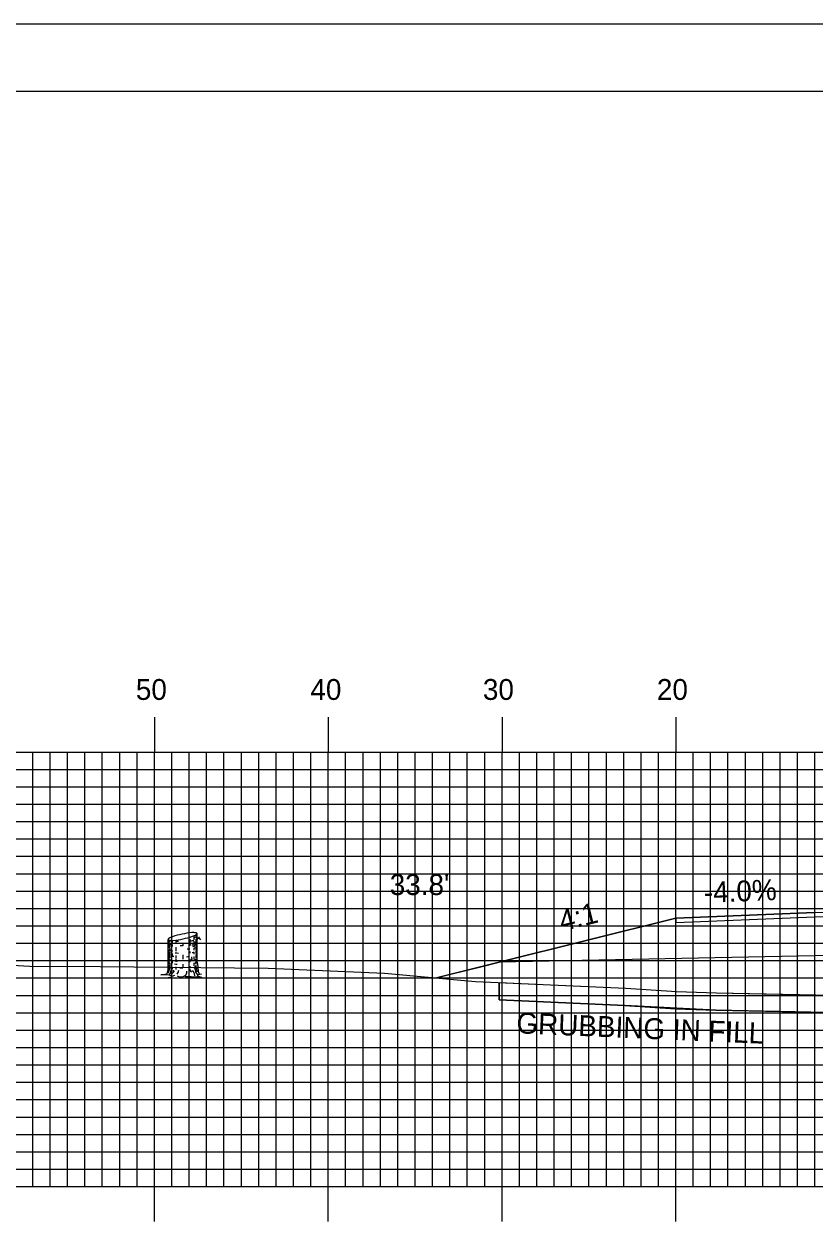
# Model space of a CAD drawing. Extents: x 1772022 to 1772366, y 442591 to 442811.
# Drawn here: x 1772130.6 to 1772176.1, y 442741.2 to 442810.5 of the extents above; entities that cross this region are included whole.
import ezdxf

# ---------------------------------------------------------------- set-up
doc = ezdxf.new("R2010")
doc.units = 0
for name, color, linetype in [('ANNOTATION', 7, 'Continuous'), ('BORDER', 7, 'Continuous'), ('D_Roadway_Centerline', 7, 'Continuous'), ('D_Roadway_Edge_Shoulder', 7, 'Continuous'), ('D_Roadway_SlopeLines', 7, 'Continuous'), ('D_Roadway_SubGrade', 7, 'Continuous'), ('D_Text_Standard', 7, 'Continuous'), ('GRUBBING IN FILL', 7, 'Continuous'), ('H_V ANNOTATION', 7, 'Continuous'), ('M_Trees_Conifer_Pay', 7, 'Continuous'), ('MAJOR', 7, 'Continuous'), ('MINOR', 7, 'Continuous'), ('PLOT BOUNDARY', 7, 'Continuous'), ('S_Roadway_Centerline', 7, 'Continuous')]:
    doc.layers.add(name, color=color, linetype=linetype)

msp = doc.modelspace()

# ---------------------------------------------------------------- linework, layer by layer
at = {"layer": 'BORDER'}
msp.add_lwpolyline([(1772038.494, 442596.665), (1772358.494, 442596.665), (1772358.494, 442806.665), (1772038.494, 442806.665)], close=True, dxfattribs=at)
at = {"layer": 'D_Roadway_Centerline'}
msp.add_lwpolyline([(1772154.321, 442755.673), (1772155.067, 442755.86), (1772156.093, 442756.116), (1772157.021, 442756.348), (1772157.919, 442756.572), (1772168.091, 442759.116), (1772168.093, 442759.116), (1772168.095, 442759.116), (1772176.094, 442759.436), (1772183.479, 442759.584), (1772188.09, 442759.676), (1772188.093, 442759.676), (1772193.883, 442759.56), (1772200.09, 442759.436), (1772200.093, 442759.436), (1772200.095, 442759.436), (1772208.094, 442759.116), (1772208.097, 442759.115), (1772218.268, 442756.572), (1772218.274, 442756.571), (1772235.086, 442752.368)], dxfattribs=at)
at = {"layer": 'D_Roadway_Edge_Shoulder'}
msp.add_lwpolyline([(1772176.094, 442759.436), (1772168.093, 442759.116), (1772168.093, 442758.866), (1772176.094, 442759.186)], close=True, dxfattribs=at)
at = {"layer": 'D_Roadway_SlopeLines'}
msp.add_lwpolyline([(1772168.093, 442759.116), (1772157.919, 442756.572), (1772156.093, 442756.116), (1772154.321, 442755.673)], dxfattribs=at)
at = {"layer": 'D_Roadway_SubGrade'}
msp.add_lwpolyline([(1772176.094, 442756.936), (1772157.919, 442756.572), (1772168.093, 442759.116), (1772168.093, 442758.866), (1772176.094, 442759.186), (1772188.093, 442759.426), (1772200.093, 442759.186), (1772208.094, 442758.866), (1772208.094, 442759.116), (1772218.268, 442756.572), (1772200.093, 442756.936), (1772188.093, 442757.176)], close=True, dxfattribs=at)
at = {"layer": 'GRUBBING IN FILL'}
msp.add_line((1772157.919, 442755.405), (1772157.919, 442754.404), dxfattribs=at)
msp.add_line((1772157.919, 442755.405), (1772157.919, 442754.404), dxfattribs=at)
msp.add_lwpolyline([(1772157.919, 442755.405), (1772160.888, 442755.272), (1772165.211, 442755.078), (1772168.132, 442754.881), (1772170.426, 442754.81), (1772180.442, 442754.609), (1772185.641, 442754.505), (1772188.094, 442754.456), (1772188.094, 442753.455), (1772180.417, 442753.609), (1772170.4, 442753.81), (1772165.155, 442754.08), (1772157.919, 442754.404)], close=True, dxfattribs=at)
msp.add_lwpolyline([(1772157.919, 442755.405), (1772160.888, 442755.272), (1772165.211, 442755.078), (1772168.132, 442754.881), (1772170.426, 442754.81), (1772180.442, 442754.609), (1772185.641, 442754.505), (1772188.094, 442754.456), (1772188.094, 442753.455), (1772180.417, 442753.609), (1772170.4, 442753.81), (1772165.155, 442754.08), (1772157.919, 442754.404)], close=True, dxfattribs=at)
msp.add_lwpolyline([(1772157.919, 442754.404), (1772165.155, 442754.08), (1772168.083, 442753.882), (1772170.4, 442753.81), (1772190.435, 442753.408), (1772192.574, 442753.345), (1772202.543, 442752.825), (1772212.888, 442752.544), (1772215.62, 442752.389), (1772218.268, 442752.3)], dxfattribs=at)
msp.add_lwpolyline([(1772157.919, 442754.404), (1772165.155, 442754.08), (1772168.083, 442753.882), (1772170.4, 442753.81), (1772190.435, 442753.408), (1772192.574, 442753.345), (1772202.543, 442752.825), (1772212.888, 442752.544), (1772215.62, 442752.389), (1772218.268, 442752.3)], dxfattribs=at)
at = {"layer": 'M_Trees_Conifer_Pay'}
for p, q in [((1772140.47, 442758.147), (1772140.47, 442757.985)), ((1772140.542, 442756.572), (1772140.542, 442758.219)), ((1772138.878, 442756.162), (1772138.878, 442757.884)), ((1772138.925, 442757.847), (1772138.925, 442757.376)), ((1772138.983, 442757.836), (1772138.983, 442757.738)), ((1772138.983, 442757.664), (1772138.983, 442757.46)), ((1772139.108, 442757.828), (1772139.108, 442757.595)), ((1772139.108, 442757.555), (1772139.108, 442757.481)), ((1772139.328, 442757.848), (1772139.328, 442757.68)), ((1772139.328, 442757.443), (1772139.328, 442757.206)), ((1772139.734, 442757.616), (1772139.734, 442757.521)), ((1772140.124, 442757.89), (1772140.124, 442757.691)), ((1772140.124, 442757.633), (1772140.124, 442757.544)), ((1772140.353, 442758.086), (1772140.353, 442757.863)), ((1772140.353, 442757.775), (1772140.353, 442757.727)), ((1772140.41, 442757.591), (1772140.358, 442757.532)), ((1772140.47, 442757.917), (1772140.47, 442757.789)), ((1772140.47, 442757.602), (1772140.47, 442757.266)), ((1772138.925, 442757.311), (1772138.925, 442757.003)), ((1772138.925, 442756.956), (1772138.925, 442756.464)), ((1772138.983, 442757.402), (1772138.983, 442757.202)), ((1772138.983, 442757.155), (1772138.983, 442756.819)), ((1772138.983, 442756.766), (1772138.983, 442756.63)), ((1772139.108, 442757.077), (1772139.108, 442756.939)), ((1772139.328, 442756.962), (1772139.328, 442756.809)), ((1772139.328, 442756.766), (1772139.328, 442756.593)), ((1772139.734, 442757.003), (1772139.734, 442756.929)), ((1772139.734, 442756.904), (1772139.734, 442756.756)), ((1772140.124, 442757.196), (1772140.124, 442757.091)), ((1772140.353, 442757.392), (1772140.353, 442757.26)), ((1772140.353, 442757.149), (1772140.353, 442757.04)), ((1772140.353, 442756.904), (1772140.353, 442756.762)), ((1772140.47, 442757.229), (1772140.47, 442757.067)), ((1772140.47, 442757.019), (1772140.47, 442756.803)), ((1772140.47, 442756.772), (1772140.47, 442756.698)), ((1772138.925, 442756.41), (1772138.925, 442756.162)), ((1772138.983, 442756.531), (1772138.983, 442756.153)), ((1772139.108, 442756.667), (1772139.108, 442756.525)), ((1772139.108, 442756.263), (1772139.108, 442756.169)), ((1772139.328, 442756.315), (1772139.328, 442756.162)), ((1772139.734, 442756.464), (1772139.734, 442756.311)), ((1772140.124, 442756.725), (1772140.124, 442756.578)), ((1772140.124, 442756.346), (1772140.124, 442756.258)), ((1772140.353, 442756.535), (1772140.353, 442756.362)), ((1772140.47, 442756.657), (1772140.47, 442756.484)), ((1772139.108, 442755.769), (1772139.271, 442755.833)), ((1772139.546, 442755.705), (1772139.42, 442755.769))]:
    msp.add_line(p, q, dxfattribs=at)
for points in [[(1772140.325, 442757.68), (1772140.294, 442757.595), (1772140.29, 442757.528), (1772140.321, 442757.464)], [(1772140.358, 442757.717), (1772140.395, 442757.643), (1772140.442, 442757.7), (1772140.5, 442757.769), (1772140.593, 442757.962), (1772140.657, 442758.009), (1772140.688, 442758.016)], [(1772140.373, 442757.464), (1772140.41, 442757.591), (1772140.473, 442757.707), (1772140.504, 442757.775), (1772140.573, 442757.921)], [(1772140.587, 442757.95), (1772140.663, 442757.958), (1772140.735, 442757.859)], [(1772139.057, 442757.19), (1772139.051, 442757.285), (1772139.094, 442757.262), (1772139.094, 442757.168)], [(1772140.196, 442756.791), (1772140.208, 442756.714), (1772140.255, 442756.725), (1772140.243, 442756.891)], [(1772140.542, 442756.572), (1772140.593, 442756.311), (1772140.609, 442756.037), (1772140.667, 442755.912), (1772140.803, 442755.881), (1772140.572, 442755.843), (1772140.572, 442755.843), (1772140.578, 442755.796), (1772140.826, 442755.702), (1772140.551, 442755.718), (1772140.196, 442755.738), (1772139.874, 442755.728), (1772139.881, 442755.811), (1772139.733, 442755.728), (1772139.546, 442755.705), (1772139.57, 442755.637), (1772139.302, 442755.681), (1772139.082, 442755.654), (1772138.789, 442755.671), (1772139.078, 442755.728), (1772139.108, 442755.769), (1772138.946, 442755.827), (1772138.709, 442755.838), (1772138.468, 442755.838), (1772138.81, 442755.895), (1772138.851, 442755.975), (1772138.878, 442756.162)], [(1772138.925, 442756.115), (1772138.904, 442756.037), (1772138.884, 442755.943)], [(1772139.004, 442756.095), (1772139.009, 442755.979), (1772138.956, 442755.891), (1772138.946, 442755.827)], [(1772139.166, 442756.122), (1772139.166, 442755.99), (1772139.078, 442755.891)], [(1772139.393, 442755.881), (1772139.46, 442755.975), (1772139.487, 442756.115)], [(1772139.881, 442755.811), (1772139.955, 442755.952), (1772139.965, 442756.053)], [(1772140.131, 442756.179), (1772140.142, 442756.053), (1772140.216, 442756.01)], [(1772140.41, 442755.79), (1772140.395, 442755.928), (1772140.321, 442756.057)], [(1772140.368, 442756.284), (1772140.442, 442756.179), (1772140.447, 442756.006), (1772140.572, 442755.843)], [(1772140.467, 442756.43), (1772140.473, 442756.284), (1772140.521, 442756.216), (1772140.531, 442756.017)]]:
    msp.add_lwpolyline(points, dxfattribs=at)
for centre, radius, start, end in [((1772140.733, 442753.117), 5.179, 101.7194, 108.05939), ((1772140.733, 442753.117), 5.179, 95.37941, 101.7194), ((1772140.323, 442757.475), 0.802, 79.2194, 95.37941), ((1772140.043, 442758.825), 0.802, 288.05939, 304.2194), ((1772140.426, 442758.016), 0.251, 71.05013, 79.2194), ((1772140.353, 442758.37), 0.251, 304.2194, 312.38868), ((1772140.481, 442758.176), 0.0817, 56.7194, 71.05013), ((1772140.467, 442758.245), 0.0817, 312.38868, 326.7194), ((1772140.497, 442758.2), 0.0527, 46.92298, 56.7194), ((1772140.511, 442758.215), 0.0314, 34.2194, 46.92298), ((1772140.491, 442758.229), 0.0527, 326.7194, 336.51582), ((1772140.516, 442758.218), 0.0264, 23.40735, 34.2194), ((1772140.51, 442758.221), 0.0314, 336.51582, 349.2194), ((1772140.519, 442758.22), 0.0226, 11.7194, 23.40735), ((1772140.519, 442758.22), 0.0226, 0.03145, 11.7194), ((1772140.515, 442758.22), 0.0264, 349.2194, 0.03145), ((1772138.91, 442757.706), 0.0334, 163.94846, 180), ((1772138.91, 442757.706), 0.0334, 180, 196.05154), ((1772138.909, 442757.883), 0.0314, 156.51582, 169.2194), ((1772138.904, 442757.884), 0.0264, 169.2194, 180.03145), ((1772138.9, 442757.884), 0.0226, 180.03145, 191.7194), ((1772138.9, 442757.884), 0.0226, 191.7194, 203.40735), ((1772138.92, 442757.709), 0.0441, 196.05154, 210), ((1772138.929, 442757.874), 0.0527, 146.7194, 156.51582), ((1772138.904, 442757.885), 0.0264, 203.40735, 214.2194), ((1772138.908, 442757.888), 0.0314, 214.2194, 226.92298), ((1772138.936, 442757.718), 0.0624, 210, 228.74941), ((1772138.953, 442757.859), 0.0817, 132.38868, 146.7194), ((1772138.922, 442757.904), 0.0527, 226.92298, 236.7194), ((1772138.938, 442757.928), 0.0817, 236.7194, 251.05013), ((1772139.008, 442757.801), 0.172, 228.74941, 240), ((1772139.067, 442757.734), 0.251, 124.2194, 132.38868), ((1772138.993, 442758.088), 0.251, 251.05013, 259.2194), ((1772139.208, 442758.146), 0.571, 240, 240.33672), ((1772139.209, 442757.935), 0.571, 240, 247.05866), ((1772139.376, 442757.278), 0.802, 108.05939, 124.2194), ((1772139.096, 442758.629), 0.802, 259.2194, 275.37941), ((1772139.208, 442758.146), 0.571, 246.85973, 257.98457), ((1772138.686, 442762.987), 5.179, 275.37941, 281.7194), ((1772139.71, 442761.896), 4.124, 264.6955, 266.73309), ((1772139.708, 442761.663), 4.124, 268.07512, 270), ((1772139.708, 442761.663), 4.124, 270, 270.35814), ((1772138.686, 442762.987), 5.179, 281.7194, 288.05939), ((1772139.708, 442761.663), 4.124, 275.78493, 277.05584), ((1772139.71, 442761.896), 4.124, 276.23804, 278.1032), ((1772140.211, 442758.379), 0.571, 278.1032, 284.36665), ((1772140.211, 442758.533), 0.571, 284.43166, 292.41325), ((1772140.211, 442758.379), 0.571, 297.0237, 300), ((1772140.41, 442758.188), 0.172, 300, 311.25059), ((1772140.41, 442758.033), 0.172, 300, 311.25059), ((1772140.482, 442758.105), 0.0624, 311.25059, 330), ((1772140.482, 442757.951), 0.0624, 311.25059, 330), ((1772140.498, 442758.096), 0.0441, 330, 343.94846), ((1772140.498, 442757.942), 0.0441, 330, 343.94846), ((1772140.508, 442757.495), 0.0334, 343.94846, 354.21506), ((1772140.508, 442758.093), 0.0334, 343.94846, 354.21506), ((1772140.508, 442757.939), 0.0334, 343.94846, 354.21506), ((1772138.91, 442757.259), 0.0334, 163.94846, 180), ((1772138.91, 442757.259), 0.0334, 180, 196.05154), ((1772138.91, 442757.049), 0.0334, 163.94846, 180), ((1772138.91, 442757.049), 0.0334, 180, 196.05154), ((1772138.91, 442756.812), 0.0334, 163.94846, 180), ((1772138.91, 442756.812), 0.0334, 180, 196.05154), ((1772138.92, 442757.262), 0.0441, 196.05154, 210), ((1772138.92, 442757.052), 0.0441, 196.05154, 210), ((1772138.92, 442756.815), 0.0441, 196.05154, 210), ((1772138.936, 442757.271), 0.0624, 210, 228.74941), ((1772138.936, 442757.061), 0.0624, 210, 228.74941), ((1772138.936, 442756.824), 0.0624, 210, 228.74941), ((1772139.008, 442757.354), 0.172, 228.74941, 240), ((1772139.008, 442757.144), 0.172, 228.74941, 240), ((1772139.008, 442756.907), 0.172, 228.74941, 240), ((1772139.208, 442757.699), 0.571, 240, 240.33672), ((1772139.208, 442757.489), 0.571, 240, 246.85973), ((1772139.208, 442757.252), 0.571, 240, 246.85973), ((1772139.208, 442757.489), 0.571, 259.27072, 261.8968), ((1772139.708, 442761.006), 4.124, 261.8968, 263.14738), ((1772139.708, 442761.216), 4.124, 264.08098, 266.66759), ((1772139.708, 442761.006), 4.124, 270, 270.35814), ((1772139.708, 442761.006), 4.124, 273.14934, 275.45691), ((1772139.71, 442761.452), 4.124, 273.70524, 275.95043), ((1772139.708, 442761.216), 4.124, 277.61247, 278.1032), ((1772140.209, 442757.699), 0.571, 278.1032, 286.92962), ((1772140.21, 442757.935), 0.571, 284.44928, 297.04285), ((1772140.209, 442757.252), 0.571, 285.39827, 297.18959), ((1772140.209, 442757.699), 0.571, 297.18959, 300), ((1772140.209, 442757.489), 0.571, 297.18959, 300), ((1772140.408, 442757.354), 0.172, 300, 311.25059), ((1772140.408, 442757.144), 0.172, 300, 311.25059), ((1772140.481, 442757.271), 0.0624, 311.25059, 330), ((1772140.481, 442757.061), 0.0624, 311.25059, 330), ((1772140.497, 442757.262), 0.0441, 330, 343.94846), ((1772140.497, 442757.052), 0.0441, 330, 343.94846), ((1772140.507, 442757.259), 0.0334, 343.94846, 354.21506), ((1772140.507, 442757.049), 0.0334, 343.94846, 354.21506), ((1772138.91, 442756.615), 0.0334, 163.94846, 180), ((1772138.91, 442756.419), 0.0334, 163.94846, 180), ((1772138.91, 442756.419), 0.0334, 180, 196.05154), ((1772138.91, 442756.199), 0.0334, 163.94846, 180), ((1772138.91, 442756.199), 0.0334, 180, 196.05154), ((1772138.92, 442756.422), 0.0441, 196.05154, 210), ((1772138.92, 442756.202), 0.0441, 196.05154, 210), ((1772138.936, 442756.431), 0.0624, 210, 228.74941), ((1772138.936, 442756.211), 0.0624, 210, 228.74941), ((1772139.008, 442756.514), 0.172, 228.74941, 240), ((1772139.008, 442756.293), 0.172, 228.74941, 240), ((1772139.197, 442757.06), 0.571, 241.23686, 248.02677), ((1772139.208, 442756.859), 0.571, 240, 246.85973), ((1772139.208, 442756.638), 0.571, 240, 244.53138), ((1772139.708, 442760.156), 4.124, 262.44379, 263.51202), ((1772139.708, 442760.572), 4.124, 263.49906, 265.83975), ((1772139.708, 442760.77), 4.124, 264.71603, 266.31934), ((1772139.708, 442760.376), 4.124, 267.81166, 270), ((1772139.708, 442760.376), 4.124, 270, 270.13279), ((1772139.708, 442760.376), 4.124, 275.78493, 276.78961), ((1772139.708, 442760.156), 4.124, 277.36842, 278.1032), ((1772140.209, 442756.638), 0.571, 278.1032, 281.63703), ((1772140.209, 442756.859), 0.571, 288.50673, 297.27208), ((1772140.209, 442757.054), 0.571, 289.29072, 300), ((1772140.408, 442756.709), 0.172, 300, 311.25059), ((1772140.408, 442756.293), 0.172, 300, 311.25059), ((1772140.481, 442756.627), 0.0624, 311.25059, 330), ((1772140.481, 442756.211), 0.0624, 311.25059, 330), ((1772140.497, 442756.618), 0.0441, 330, 343.94846), ((1772140.497, 442756.202), 0.0441, 330, 343.94846), ((1772140.507, 442756.615), 0.0334, 343.94846, 354.21506), ((1772140.507, 442756.199), 0.0334, 343.94846, 354.21506)]:
    msp.add_arc(centre, radius, start, end, dxfattribs=at)
at = {"layer": 'MAJOR'}
for p, q in [((1772138.094, 442770.669), (1772138.094, 442768.665)), ((1772148.094, 442770.669), (1772148.094, 442768.665)), ((1772158.094, 442770.669), (1772158.094, 442768.665)), ((1772168.094, 442770.669), (1772168.094, 442768.665)), ((1772048.094, 442768.665), (1772328.094, 442768.665)), ((1772048.094, 442768.665), (1772328.094, 442768.665)), ((1772138.094, 442743.665), (1772138.094, 442768.665)), ((1772148.094, 442743.665), (1772148.094, 442768.665)), ((1772158.094, 442743.665), (1772158.094, 442768.665)), ((1772168.094, 442743.665), (1772168.094, 442768.665)), ((1772048.094, 442763.665), (1772328.094, 442763.665)), ((1772048.094, 442758.665), (1772328.094, 442758.665)), ((1772048.094, 442753.665), (1772328.094, 442753.665)), ((1772048.094, 442748.665), (1772328.094, 442748.665)), ((1772048.094, 442743.665), (1772328.094, 442743.665)), ((1772048.094, 442743.665), (1772328.094, 442743.665)), ((1772138.094, 442741.661), (1772138.094, 442743.665)), ((1772148.094, 442741.661), (1772148.094, 442743.665)), ((1772158.094, 442741.661), (1772158.094, 442743.665)), ((1772168.094, 442741.661), (1772168.094, 442743.665))]:
    msp.add_line(p, q, dxfattribs=at)
at = {"layer": 'MINOR'}
for p, q in [((1772131.094, 442743.665), (1772131.094, 442768.665)), ((1772132.094, 442743.665), (1772132.094, 442768.665)), ((1772133.094, 442743.665), (1772133.094, 442768.665)), ((1772134.094, 442743.665), (1772134.094, 442768.665)), ((1772135.094, 442743.665), (1772135.094, 442768.665)), ((1772136.094, 442743.665), (1772136.094, 442768.665)), ((1772137.094, 442743.665), (1772137.094, 442768.665)), ((1772139.094, 442743.665), (1772139.094, 442768.665)), ((1772140.094, 442743.665), (1772140.094, 442768.665)), ((1772141.094, 442743.665), (1772141.094, 442768.665)), ((1772142.094, 442743.665), (1772142.094, 442768.665)), ((1772143.094, 442743.665), (1772143.094, 442768.665)), ((1772144.094, 442743.665), (1772144.094, 442768.665)), ((1772145.094, 442743.665), (1772145.094, 442768.665)), ((1772146.094, 442743.665), (1772146.094, 442768.665)), ((1772147.094, 442743.665), (1772147.094, 442768.665)), ((1772149.094, 442743.665), (1772149.094, 442768.665)), ((1772150.094, 442743.665), (1772150.094, 442768.665)), ((1772151.094, 442743.665), (1772151.094, 442768.665)), ((1772152.094, 442743.665), (1772152.094, 442768.665)), ((1772153.094, 442743.665), (1772153.094, 442768.665)), ((1772154.094, 442743.665), (1772154.094, 442768.665)), ((1772155.094, 442743.665), (1772155.094, 442768.665)), ((1772156.094, 442743.665), (1772156.094, 442768.665)), ((1772157.094, 442743.665), (1772157.094, 442768.665)), ((1772159.094, 442743.665), (1772159.094, 442768.665)), ((1772160.094, 442743.665), (1772160.094, 442768.665)), ((1772161.094, 442743.665), (1772161.094, 442768.665)), ((1772162.094, 442743.665), (1772162.094, 442768.665)), ((1772163.094, 442743.665), (1772163.094, 442768.665)), ((1772164.094, 442743.665), (1772164.094, 442768.665)), ((1772165.094, 442743.665), (1772165.094, 442768.665)), ((1772166.094, 442743.665), (1772166.094, 442768.665)), ((1772167.094, 442743.665), (1772167.094, 442768.665)), ((1772169.094, 442743.665), (1772169.094, 442768.665)), ((1772170.094, 442743.665), (1772170.094, 442768.665)), ((1772171.094, 442743.665), (1772171.094, 442768.665)), ((1772172.094, 442743.665), (1772172.094, 442768.665)), ((1772173.094, 442743.665), (1772173.094, 442768.665)), ((1772174.094, 442743.665), (1772174.094, 442768.665)), ((1772175.094, 442743.665), (1772175.094, 442768.665)), ((1772176.094, 442743.665), (1772176.094, 442768.665)), ((1772048.094, 442767.665), (1772328.094, 442767.665)), ((1772048.094, 442766.665), (1772328.094, 442766.665)), ((1772048.094, 442765.665), (1772328.094, 442765.665)), ((1772048.094, 442764.665), (1772328.094, 442764.665)), ((1772048.094, 442762.665), (1772328.094, 442762.665)), ((1772048.094, 442761.665), (1772328.094, 442761.665)), ((1772048.094, 442760.665), (1772328.094, 442760.665)), ((1772048.094, 442759.665), (1772328.094, 442759.665)), ((1772048.094, 442757.665), (1772328.094, 442757.665)), ((1772048.094, 442756.665), (1772328.094, 442756.665)), ((1772048.094, 442755.665), (1772328.094, 442755.665)), ((1772048.094, 442754.665), (1772328.094, 442754.665)), ((1772048.094, 442752.665), (1772328.094, 442752.665)), ((1772048.094, 442751.665), (1772328.094, 442751.665)), ((1772048.094, 442750.665), (1772328.094, 442750.665)), ((1772048.094, 442749.665), (1772328.094, 442749.665)), ((1772048.094, 442747.665), (1772328.094, 442747.665)), ((1772048.094, 442746.665), (1772328.094, 442746.665)), ((1772048.094, 442745.665), (1772328.094, 442745.665)), ((1772048.094, 442744.665), (1772328.094, 442744.665))]:
    msp.add_line(p, q, dxfattribs=at)
at = {"layer": 'PLOT BOUNDARY'}
msp.add_lwpolyline([(1772022.307, 442590.547), (1772362.307, 442590.547), (1772362.307, 442810.547), (1772022.307, 442810.547)], close=True, dxfattribs=at)
at = {"layer": 'S_Roadway_Centerline'}
msp.add_lwpolyline([(1772110.178, 442757.521), (1772130.932, 442756.345), (1772134.969, 442756.324), (1772144.642, 442756.221), (1772151.333, 442755.949), (1772156.564, 442755.465), (1772165.211, 442755.078), (1772168.132, 442754.881), (1772170.426, 442754.81), (1772190.459, 442754.408), (1772192.615, 442754.344), (1772202.582, 442753.824), (1772212.93, 442753.543), (1772215.665, 442753.389), (1772218.582, 442753.29), (1772233.532, 442752.414), (1772245.555, 442752.053)], dxfattribs=at)

# ---------------------------------------------------------------- texts
at = {"layer": 'ANNOTATION'}
for s, rotation, p in [('-4.0%', 2.29044, (1772169.726, 442759.983)), ('4:1', 14.03894, (1772161.541, 442758.339))]:
    msp.add_text(s, height=1.2, rotation=rotation, dxfattribs=at).set_placement(p)
at = {"layer": 'D_Text_Standard'}
msp.add_text("33.8'", height=1.2, dxfattribs=at).set_placement((1772151.63, 442760.438))
at = {"layer": 'GRUBBING IN FILL'}
msp.add_text('GRUBBING IN FILL', height=1.2, rotation=357.57187, dxfattribs=at).set_placement((1772158.899, 442752.487))
at = {"layer": 'H_V ANNOTATION'}
for s, p in [('50', (1772137.023, 442771.665)), ('40', (1772147.066, 442771.665)), ('30', (1772156.991, 442771.665)), ('20', (1772167.002, 442771.665))]:
    msp.add_text(s, height=1.2, dxfattribs=at).set_placement(p)

doc.saveas('drawing.dxf')
